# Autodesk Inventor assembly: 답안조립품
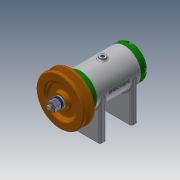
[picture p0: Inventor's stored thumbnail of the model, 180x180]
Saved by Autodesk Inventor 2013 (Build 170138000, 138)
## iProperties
Created: 2020-07
Part Number: 답안조립품
Document SubType Name: Assembly
Designer: user
Author: user
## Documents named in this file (15)
- C:\Users\user\Desktop\답안조립품.iam
- C:\Users\user\Desktop\본체.ipt
- C:\Users\user\Desktop\700706V1035\Ű 3x3x12.ipt
- C:\Users\user\Desktop\700706V1035\V벨트풀리.ipt
- C:\Users\user\Desktop\700706V1035\너트 M8.ipt
- C:\Users\user\Desktop\700706V1035\뒤커버.ipt
- C:\Users\user\Desktop\700706V1035\베어링 6002.ipt
- C:\Users\user\Desktop\700706V1035\볼트 M4x12.ipt
- C:\Users\user\Desktop\700706V1035\볼트 M6x8.ipt
- C:\Users\user\Desktop\700706V1035\스프링와셔 8.ipt
- C:\Users\user\Desktop\700706V1035\앞커버.ipt
- C:\Users\user\Desktop\700706V1035\오일 실 15 25 7.ipt
- C:\Users\user\Desktop\700706V1035\와셔 6x11.5.ipt
- C:\Users\user\Desktop\700706V1035\와셔 8x17.ipt
- C:\Users\user\Desktop\700706V1035\축.ipt
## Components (2 placed, 2 different names)
1. Ű 3x3x12:1
2. V벨트풀리:1
